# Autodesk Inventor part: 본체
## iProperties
Created: 2015-01
Part Number: 본체
Document SubType Name: Modeling
Designer: elite
Density: 2.71 g/cm^3
Material: 알루미늄-6061
Mass: 1021.41 g
Surface Area: 1060.81 cm^2
Volume: 376.905 cm^3
Author: elite
